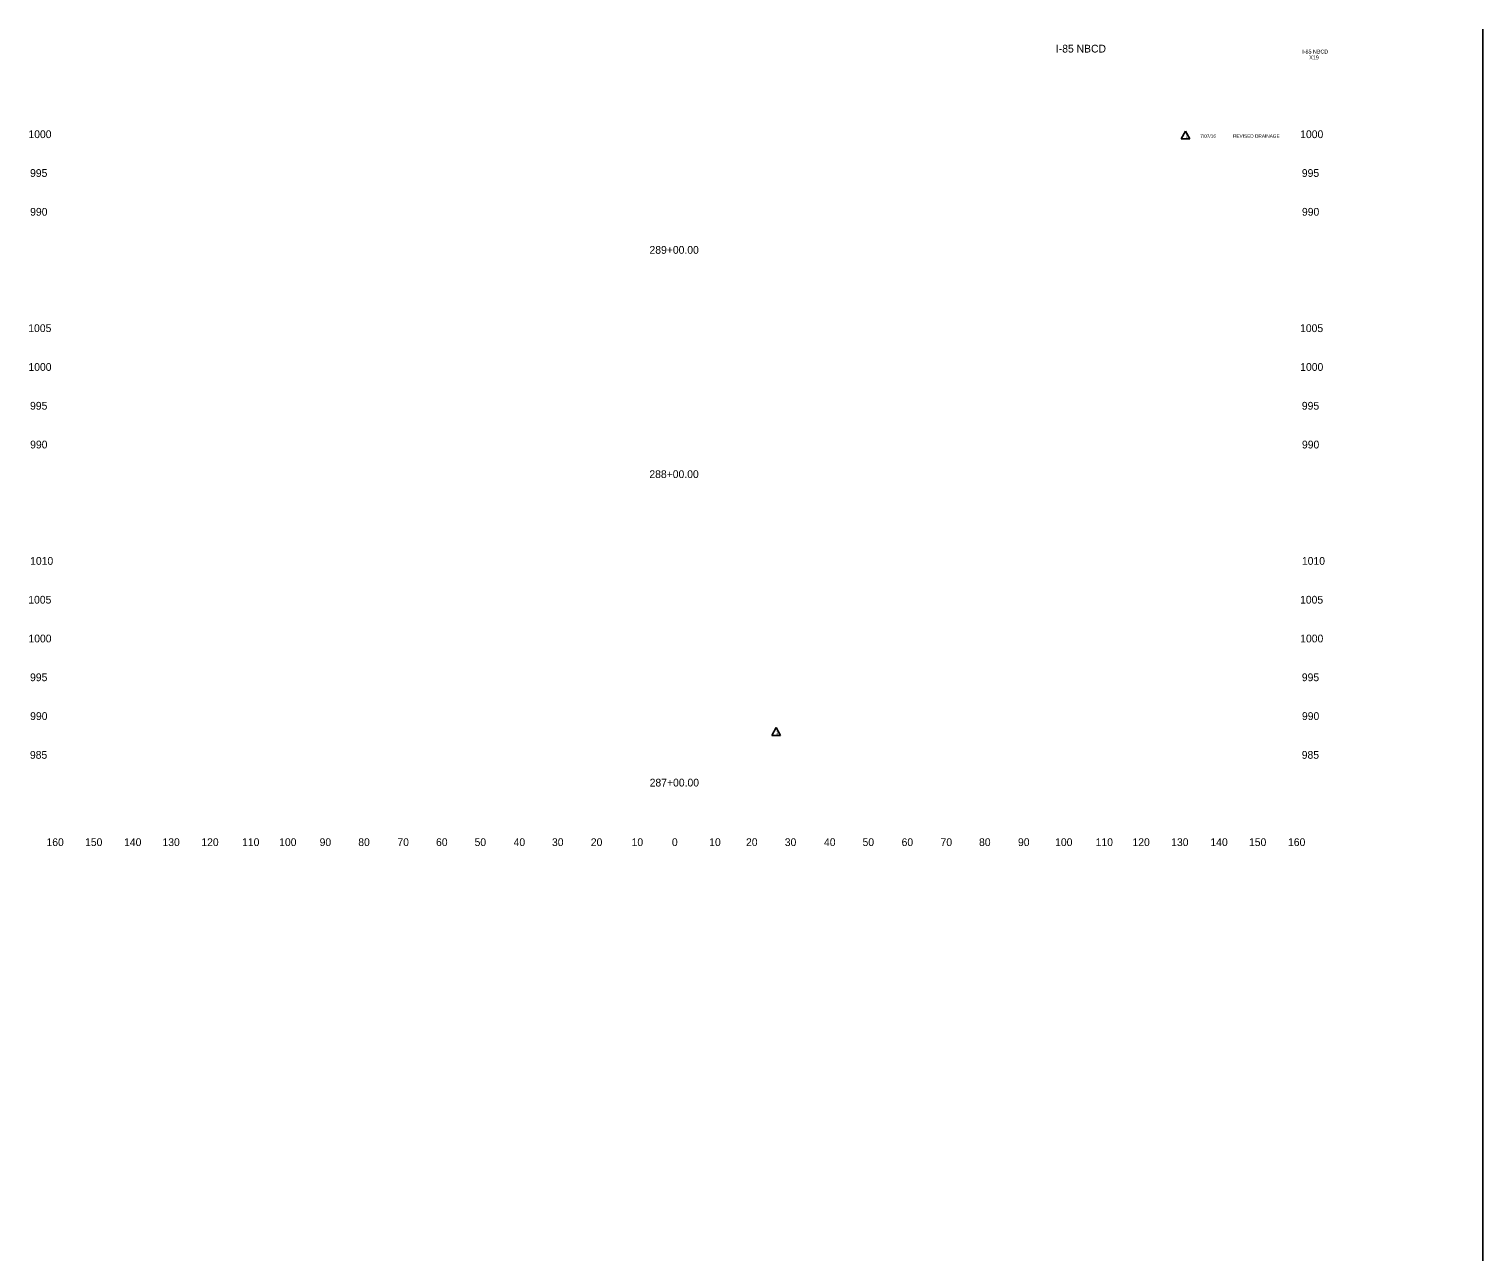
# Model space of a CAD drawing. Extents: x 4994 to 6358, y 4997 to 8804.
# Drawn here: x 5508.6 to 5883.3, y 8092.9 to 8408.1 of the extents above; entities that cross this region are included whole.
import ezdxf

# ---------------------------------------------------------------- set-up
doc = ezdxf.new("R2010")
doc.units = 0
for name, color, linetype in [('RD_SHT_ID', 7, 'Continuous'), ('RD_SHT_TX', 7, 'Continuous'), ('RD_XS_TX_Offset', 7, 'Continuous'), ('RD_XS_TX_Station', 7, 'Continuous')]:
    doc.layers.add(name, color=color, linetype=linetype)

msp = doc.modelspace()

# ---------------------------------------------------------------- linework, layer by layer
at = {"layer": 'RD_SHT_ID'}
msp.add_line((5883.33, 8408.11), (5883.33, 7777.63), dxfattribs=at)
at = {"layer": 'RD_SHT_TX'}
for p, q in [((5806.69, 8381.82), (5805.56, 8379.79)), ((5805.56, 8379.79), (5807.83, 8379.79)), ((5806.69, 8381.82), (5807.83, 8379.79)), ((5701.15, 8228.04), (5700.01, 8226.01)), ((5700.01, 8226.01), (5702.29, 8226.01)), ((5701.15, 8228.04), (5702.29, 8226.01))]:
    msp.add_line(p, q, dxfattribs=at)

# ---------------------------------------------------------------- texts
at = {"layer": 'RD_SHT_ID'}
for s, height, p in [('I-85 NBCD', 2, (5773.26, 8402.06)), ('I-85 NBCD', 1, (5836.77, 8401.8)), ('X19', 1, (5838.57, 8400.3))]:
    msp.add_text(s, height=height, dxfattribs=at).set_placement(p)
at = {"layer": 'RD_SHT_TX'}
for s, p in [('1', (5806.69, 8380.11)), ('7/07/16', (5810.47, 8380.08)), ('REVISED DRAINAGE', (5818.92, 8380.08)), ('1', (5701.15, 8226.34))]:
    msp.add_text(s, height=0.88, dxfattribs=at).set_placement(p)
at = {"layer": 'RD_XS_TX_Offset'}
for s, p in [('1000', (5508.44, 8380)), ('1000', (5836.24, 8380)), ('995', (5508.86, 8370)), ('995', (5836.66, 8370)), ('990', (5508.89, 8360)), ('990', (5836.69, 8360)), ('1005', (5508.4, 8330)), ('1005', (5836.2, 8330)), ('1000', (5508.44, 8320)), ('1000', (5836.24, 8320)), ('995', (5508.86, 8310)), ('995', (5836.66, 8310)), ('990', (5508.89, 8300)), ('990', (5836.69, 8300)), ('1010', (5508.88, 8270)), ('1010', (5836.68, 8270)), ('1005', (5508.4, 8260)), ('1005', (5836.2, 8260)), ('1000', (5508.44, 8250)), ('1000', (5836.24, 8250)), ('995', (5508.86, 8240)), ('995', (5836.66, 8240)), ('990', (5508.89, 8230)), ('990', (5836.69, 8230)), ('985', (5508.83, 8220)), ('985', (5836.63, 8220)), ('160', (5513.1, 8197.5)), ('150', (5523.04, 8197.5)), ('140', (5533.1, 8197.5)), ('130', (5542.99, 8197.5)), ('120', (5553.01, 8197.5)), ('110', (5563.51, 8197.5)), ('100', (5573.07, 8197.5)), ('90', (5583.5, 8197.5)), ('80', (5593.46, 8197.5)), ('70', (5603.54, 8197.5)), ('60', (5613.5, 8197.5)), ('50', (5623.43, 8197.5)), ('40', (5633.5, 8197.5)), ('30', (5643.39, 8197.5)), ('20', (5653.4, 8197.5)), ('10', (5663.91, 8197.5)), ('0', (5674.3, 8197.5)), ('0', (5674.3, 8197.5)), ('10', (5683.91, 8197.5)), ('20', (5693.4, 8197.5)), ('30', (5703.39, 8197.5)), ('40', (5713.5, 8197.5)), ('50', (5723.43, 8197.5)), ('60', (5733.5, 8197.5)), ('70', (5743.54, 8197.5)), ('80', (5753.46, 8197.5)), ('90', (5763.5, 8197.5)), ('100', (5773.07, 8197.5)), ('110', (5783.51, 8197.5)), ('120', (5793.01, 8197.5)), ('130', (5802.99, 8197.5)), ('140', (5813.1, 8197.5)), ('150', (5823.04, 8197.5)), ('160', (5833.1, 8197.5))]:
    msp.add_text(s, height=2, dxfattribs=at).set_placement(p)
at = {"layer": 'RD_XS_TX_Station'}
for s, p in [('289+00.00', (5668.52, 8350.18)), ('288+00.00', (5668.49, 8292.37)), ('287+00.00', (5668.57, 8212.85))]:
    msp.add_text(s, height=2, dxfattribs=at).set_placement(p)

doc.saveas('drawing.dxf')
